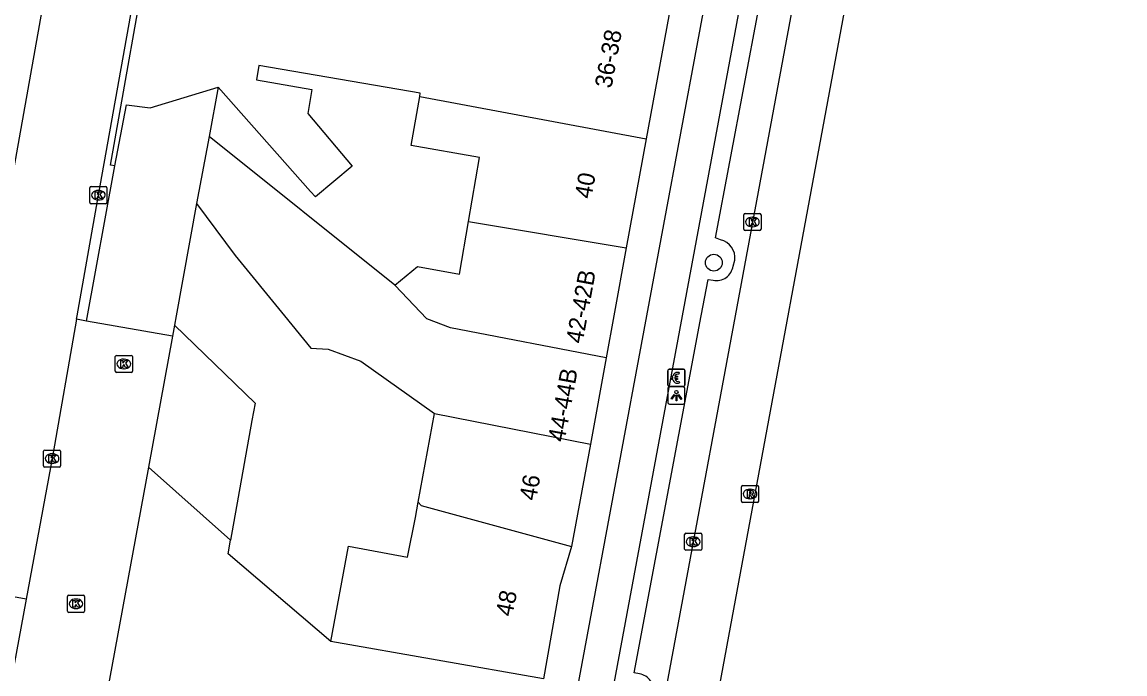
# Model space of a CAD drawing. Extents: x 161402 to 161933, y 381650 to 382313.
# Drawn here: x 161862.2 to 161926.7, y 381979.1 to 382017.2 of the extents above; entities that cross this region are included whole.
import ezdxf

# ---------------------------------------------------------------- set-up
doc = ezdxf.new("R2010")
doc.units = 0
for name, color, linetype in [('IMGEO_Betaalautomaat', 7, 'Continuous'), ('IMGEO_Boom', 7, 'Continuous'), ('IMGEO_Fietspad_gesloten', 7, 'Continuous'), ('IMGEO_Kolk', 7, 'Continuous'), ('IMGEO_Lichtpunt', 7, 'Continuous'), ('IMGEO_Muur', 7, 'Continuous'), ('IMGEO_OVBaan_gesloten', 7, 'Continuous'), ('IMGEO_Pand', 7, 'Continuous'), ('IMGEO_Pand_nummerreeks', 7, 'Continuous'), ('IMGEO_Parkeervlak_open', 7, 'Continuous'), ('IMGEO_Rijbaan_lokaal_gesloten', 7, 'Continuous'), ('IMGEO_Rijbaan_lokaal_open', 7, 'Continuous'), ('IMGEO_Rioolput', 7, 'Continuous')]:
    doc.layers.add(name, color=color, linetype=linetype)

msp = doc.modelspace()

# ---------------------------------------------------------------- linework, layer by layer
at = {"layer": 'IMGEO_Betaalautomaat'}
for p, q in [((161899.985, 381995.955), (161899.985, 381996.796)), ((161899.985, 381996.796), (161899.985, 381995.955)), ((161900.06, 381996.879), (161900.901, 381996.879)), ((161900.901, 381996.879), (161900.06, 381996.879)), ((161900.984, 381996.805), (161900.984, 381995.964)), ((161900.984, 381995.964), (161900.984, 381996.805)), ((161900.268, 381996.343), (161900.268, 381996.411)), ((161900.389, 381996.411), (161900.389, 381996.343)), ((161900.647, 381996.684), (161900.63, 381996.584)), ((161900.634, 381996.178), (161900.656, 381996.091)), ((161900.91, 381995.88), (161900.069, 381995.88)), ((161900.069, 381995.88), (161900.91, 381995.88))]:
    msp.add_line(p, q, dxfattribs=at)
for points in [[(161900.268, 381996.411), (161900.199, 381996.411), (161900.199, 381996.48), (161900.278, 381996.48)], [(161900.273, 381996.274), (161900.199, 381996.274), (161900.199, 381996.343), (161900.268, 381996.343)], [(161900.4, 381996.48), (161900.547, 381996.48), (161900.547, 381996.411), (161900.389, 381996.411)], [(161900.389, 381996.343), (161900.547, 381996.343), (161900.547, 381996.274), (161900.403, 381996.274)]]:
    msp.add_lwpolyline(points, dxfattribs=at)
for centre, radius, start, end in [((161900.063, 381996.802), 0.0779, 92.4484, 184.28452), ((161900.063, 381996.802), 0.0779, 92.4484, 184.28452), ((161900.907, 381996.802), 0.0779, 2.4484, 94.28452), ((161900.907, 381996.802), 0.0779, 2.4484, 94.28452), ((161900.534, 381996.329), 0.267, 191.80956, 297.03891), ((161900.561, 381996.404), 0.293, 73.01398, 165.01395), ((161900.567, 381996.417), 0.179, 69.32359, 159.56827), ((161900.567, 381996.344), 0.179, 202.76249, 291.86925), ((161900.063, 381995.958), 0.0779, 182.4484, 274.28452), ((161900.063, 381995.958), 0.0779, 182.4484, 274.28452), ((161900.907, 381995.958), 0.0779, 272.4484, 4.28452), ((161900.907, 381995.958), 0.0779, 272.4484, 4.28452)]:
    msp.add_arc(centre, radius, start, end, dxfattribs=at)
at = {"layer": 'IMGEO_Boom'}
msp.add_circle((161902.671, 382003.107), 0.489, dxfattribs=at)
at = {"layer": 'IMGEO_Fietspad_gesloten'}
for points in [[(161869.899, 381834.602), (161881.54, 381896.271), (161882.623, 381902.093), (161888.398, 381933.147), (161890.059, 381942.083), (161900.83, 382000), (161908.061, 382038.88), (161912.039, 382060.567)], [(161887.89, 381941.593), (161898.752, 382000), (161905.702, 382037.375), (161910.061, 382061.001)]]:
    msp.add_lwpolyline(points, dxfattribs=at)
at = {"layer": 'IMGEO_Kolk'}
for p, q in [((161866.202, 382006.623), (161866.202, 382007.475)), ((161866.277, 382007.549), (161867.129, 382007.549)), ((161866.69, 382007.329), (161866.715, 382007.329)), ((161867.203, 382007.475), (161867.203, 382006.623)), ((161867.129, 382006.549), (161866.277, 382006.549)), ((161866.713, 382006.769), (161866.688, 382006.769)), ((161904.427, 382005.056), (161904.427, 382005.908)), ((161904.502, 382005.982), (161905.354, 382005.982)), ((161904.915, 382005.762), (161904.94, 382005.762)), ((161905.428, 382005.908), (161905.428, 382005.056)), ((161904.938, 382005.202), (161904.913, 382005.202)), ((161905.354, 382004.982), (161904.502, 382004.982)), ((161867.692, 381996.764), (161867.692, 381997.616)), ((161867.767, 381997.69), (161868.619, 381997.69)), ((161868.18, 381997.47), (161868.205, 381997.47)), ((161868.693, 381997.616), (161868.693, 381996.764)), ((161868.203, 381996.91), (161868.178, 381996.91)), ((161868.619, 381996.69), (161867.767, 381996.69)), ((161863.496, 381991.235), (161863.496, 381992.087)), ((161863.571, 381992.161), (161864.423, 381992.161)), ((161863.984, 381991.941), (161864.009, 381991.941)), ((161864.497, 381992.087), (161864.497, 381991.235)), ((161864.423, 381991.161), (161863.571, 381991.161)), ((161864.007, 381991.381), (161863.982, 381991.381)), ((161900.963, 381986.38), (161900.963, 381987.232)), ((161901.038, 381987.306), (161901.89, 381987.306)), ((161901.451, 381987.086), (161901.476, 381987.086)), ((161901.964, 381987.232), (161901.964, 381986.38)), ((161901.474, 381986.526), (161901.449, 381986.526)), ((161901.89, 381986.306), (161901.038, 381986.306)), ((161864.896, 381982.754), (161864.896, 381983.606)), ((161864.971, 381983.68), (161865.823, 381983.68)), ((161865.384, 381983.46), (161865.409, 381983.46)), ((161865.897, 381983.606), (161865.897, 381982.754)), ((161865.823, 381982.68), (161864.971, 381982.68)), ((161865.407, 381982.9), (161865.382, 381982.9))]:
    msp.add_line(p, q, dxfattribs=at)
for points in [[(161866.202, 382006.623), (161866.202, 382007.475)], [(161866.277, 382007.549), (161867.129, 382007.549)], [(161866.523, 382007.249), (161866.646, 382007.249), (161866.646, 382007.098), (161866.776, 382007.249), (161866.94, 382007.249), (161866.794, 382007.098), (161866.947, 382006.849), (161866.795, 382006.849), (161866.71, 382007.013), (161866.646, 382006.946), (161866.646, 382006.849), (161866.523, 382006.849), (161866.523, 382007.249)], [(161867.203, 382007.475), (161867.203, 382006.623)], [(161867.129, 382006.549), (161866.277, 382006.549)], [(161904.427, 382005.056), (161904.427, 382005.908)], [(161904.502, 382005.982), (161905.354, 382005.982)], [(161905.428, 382005.908), (161905.428, 382005.056)], [(161904.748, 382005.682), (161904.871, 382005.682), (161904.871, 382005.531), (161905.001, 382005.682), (161905.165, 382005.682), (161905.019, 382005.531), (161905.172, 382005.282), (161905.02, 382005.282), (161904.935, 382005.446), (161904.871, 382005.379), (161904.871, 382005.282), (161904.748, 382005.282), (161904.748, 382005.682)], [(161905.354, 382004.982), (161904.502, 382004.982)], [(161867.692, 381996.764), (161867.692, 381997.616)], [(161867.767, 381997.69), (161868.619, 381997.69)], [(161868.013, 381997.39), (161868.136, 381997.39), (161868.136, 381997.239), (161868.266, 381997.39), (161868.43, 381997.39), (161868.284, 381997.239), (161868.437, 381996.99), (161868.285, 381996.99), (161868.2, 381997.154), (161868.136, 381997.087), (161868.136, 381996.99), (161868.013, 381996.99), (161868.013, 381997.39)], [(161868.693, 381997.616), (161868.693, 381996.764)], [(161868.619, 381996.69), (161867.767, 381996.69)], [(161863.496, 381991.235), (161863.496, 381992.087)], [(161863.571, 381992.161), (161864.423, 381992.161)], [(161863.817, 381991.861), (161863.94, 381991.861), (161863.94, 381991.71), (161864.07, 381991.861), (161864.234, 381991.861), (161864.088, 381991.71), (161864.241, 381991.461), (161864.089, 381991.461), (161864.004, 381991.625), (161863.94, 381991.558), (161863.94, 381991.461), (161863.817, 381991.461), (161863.817, 381991.861)], [(161864.497, 381992.087), (161864.497, 381991.235)], [(161864.423, 381991.161), (161863.571, 381991.161)], [(161900.963, 381986.38), (161900.963, 381987.232)], [(161901.038, 381987.306), (161901.89, 381987.306)], [(161901.964, 381987.232), (161901.964, 381986.38)], [(161901.284, 381987.006), (161901.407, 381987.006), (161901.407, 381986.855), (161901.537, 381987.006), (161901.701, 381987.006), (161901.555, 381986.855), (161901.708, 381986.606), (161901.556, 381986.606), (161901.471, 381986.77), (161901.407, 381986.703), (161901.407, 381986.606), (161901.284, 381986.606), (161901.284, 381987.006)], [(161901.89, 381986.306), (161901.038, 381986.306)], [(161864.896, 381982.754), (161864.896, 381983.606)], [(161864.971, 381983.68), (161865.823, 381983.68)], [(161865.217, 381983.38), (161865.34, 381983.38), (161865.34, 381983.229), (161865.47, 381983.38), (161865.634, 381983.38), (161865.488, 381983.229), (161865.641, 381982.98), (161865.489, 381982.98), (161865.404, 381983.144), (161865.34, 381983.077), (161865.34, 381982.98), (161865.217, 381982.98), (161865.217, 381983.38)], [(161865.897, 381983.606), (161865.897, 381982.754)], [(161865.823, 381982.68), (161864.971, 381982.68)]]:
    msp.add_lwpolyline(points, dxfattribs=at)
for centre, start, end in [((161866.279, 382007.473), 91.55205, 178.44795), ((161866.279, 382007.473), 91.55205, 178.44795), ((161867.127, 382007.473), 1.55205, 88.44795), ((161867.127, 382007.473), 1.55205, 88.44795), ((161866.279, 382006.625), 181.55205, 268.44795), ((161866.279, 382006.625), 181.55205, 268.44795), ((161867.127, 382006.625), 271.55205, 358.44795), ((161867.127, 382006.625), 271.55205, 358.44795), ((161904.504, 382005.906), 91.55205, 178.44795), ((161904.504, 382005.906), 91.55205, 178.44795), ((161905.352, 382005.906), 1.55205, 88.44795), ((161905.352, 382005.906), 1.55205, 88.44795), ((161904.504, 382005.058), 181.55205, 268.44795), ((161904.504, 382005.058), 181.55205, 268.44795), ((161905.352, 382005.058), 271.55205, 358.44795), ((161905.352, 382005.058), 271.55205, 358.44795), ((161867.769, 381997.614), 91.55205, 178.44795), ((161867.769, 381997.614), 91.55205, 178.44795), ((161868.617, 381997.614), 1.55205, 88.44795), ((161868.617, 381997.614), 1.55205, 88.44795), ((161867.769, 381996.766), 181.55205, 268.44795), ((161867.769, 381996.766), 181.55205, 268.44795), ((161868.617, 381996.766), 271.55205, 358.44795), ((161868.617, 381996.766), 271.55205, 358.44795), ((161863.573, 381992.085), 91.55205, 178.44795), ((161863.573, 381992.085), 91.55205, 178.44795), ((161864.421, 381992.085), 1.55205, 88.44795), ((161864.421, 381992.085), 1.55205, 88.44795), ((161863.573, 381991.237), 181.55205, 268.44795), ((161863.573, 381991.237), 181.55205, 268.44795), ((161864.421, 381991.237), 271.55205, 358.44795), ((161864.421, 381991.237), 271.55205, 358.44795), ((161901.04, 381987.23), 91.55205, 178.44795), ((161901.04, 381987.23), 91.55205, 178.44795), ((161901.888, 381987.23), 1.55205, 88.44795), ((161901.888, 381987.23), 1.55205, 88.44795), ((161901.04, 381986.382), 181.55205, 268.44795), ((161901.04, 381986.382), 181.55205, 268.44795), ((161901.888, 381986.382), 271.55205, 358.44795), ((161901.888, 381986.382), 271.55205, 358.44795), ((161864.973, 381983.604), 91.55205, 178.44795), ((161864.973, 381983.604), 91.55205, 178.44795), ((161865.821, 381983.604), 1.55205, 88.44795), ((161865.821, 381983.604), 1.55205, 88.44795), ((161864.973, 381982.756), 181.55205, 268.44795), ((161864.973, 381982.756), 181.55205, 268.44795), ((161865.821, 381982.756), 271.55205, 358.44795), ((161865.821, 381982.756), 271.55205, 358.44795)]:
    msp.add_arc(centre, 0.0765, start, end, dxfattribs=at)
for centre, major_axis, ratio, start_param, end_param in [((161866.689, 382007.049), (-0.387, 0.002), 0.722429, 4.712389, 7.853982), ((161866.714, 382007.049), (-0.39, 0.002), 0.717154, 1.570796, 4.712389), ((161904.914, 382005.482), (-0.387, 0.002), 0.722429, 4.712389, 7.853982), ((161904.939, 382005.482), (-0.39, 0.002), 0.717154, 1.570796, 4.712389), ((161868.179, 381997.19), (-0.387, 0.002), 0.722429, 4.712389, 7.853982), ((161868.204, 381997.19), (-0.39, 0.002), 0.717154, 1.570796, 4.712389), ((161863.983, 381991.661), (-0.387, 0.002), 0.722429, 4.712389, 7.853982), ((161864.008, 381991.661), (-0.39, 0.002), 0.717154, 1.570796, 4.712389), ((161901.45, 381986.806), (-0.387, 0.002), 0.722429, 4.712389, 7.853982), ((161901.475, 381986.806), (-0.39, 0.002), 0.717154, 1.570796, 4.712389), ((161865.383, 381983.18), (-0.387, 0.002), 0.722429, 4.712389, 7.853982), ((161865.408, 381983.18), (-0.39, 0.002), 0.717154, 1.570796, 4.712389)]:
    msp.add_ellipse(centre, major_axis=major_axis, ratio=ratio, start_param=start_param, end_param=end_param, dxfattribs=at)
at = {"layer": 'IMGEO_Lichtpunt'}
for p, q in [((161899.984, 381995.75), (161899.984, 381994.943)), ((161899.984, 381995.75), (161899.984, 381994.943)), ((161900.886, 381995.845), (161900.078, 381995.845)), ((161900.886, 381995.845), (161900.078, 381995.845)), ((161900.98, 381994.943), (161900.98, 381995.75)), ((161900.98, 381994.943), (161900.98, 381995.75)), ((161900.078, 381994.849), (161900.886, 381994.849)), ((161900.078, 381994.849), (161900.886, 381994.849))]:
    msp.add_line(p, q, dxfattribs=at)
for points in [[(161900.358, 381995.414), (161900.397, 381995.386), (161900.209, 381995.124), (161900.171, 381995.151), (161900.358, 381995.414)], [(161900.57, 381995.386), (161900.608, 381995.413), (161900.795, 381995.151), (161900.756, 381995.123), (161900.57, 381995.386)], [(161900.46, 381995.366), (161900.507, 381995.366), (161900.507, 381995.044), (161900.46, 381995.044), (161900.46, 381995.366)]]:
    msp.add_lwpolyline(points, dxfattribs=at)
msp.add_circle((161900.483, 381995.548), 0.0994, dxfattribs=at)
for centre, start, end in [((161900.078, 381995.75), 90, 180), ((161900.078, 381995.75), 90, 180), ((161900.886, 381995.75), 0, 90), ((161900.886, 381995.75), 0, 90), ((161900.078, 381994.943), 180, 270), ((161900.078, 381994.943), 180, 270), ((161900.886, 381994.943), 270, 0), ((161900.886, 381994.943), 270, 360)]:
    msp.add_arc(centre, 0.0946, start, end, dxfattribs=at)
at = {"layer": 'IMGEO_Muur'}
for points in [[(161865.428, 381999.797), (161865.464, 382000), (161866.704, 382007.049), (161869.364, 382021.87), (161869.415, 382022.052), (161864.341, 382023.003)], [(161866.018, 381999.693), (161867.662, 382008.757)], [(161866.018, 381999.693), (161865.428, 381999.797)]]:
    msp.add_lwpolyline(points, dxfattribs=at)
at = {"layer": 'IMGEO_OVBaan_gesloten'}
msp.add_lwpolyline([(161894.174, 381930.698), (161920.066, 382070.485), (161920.568, 382072.989), (161920.797, 382074.121), (161926.695, 382099.95)], dxfattribs=at)
at = {"layer": 'IMGEO_Pand'}
for points in [[(161867.662, 382008.757), (161867.411, 382008.805), (161869.815, 382022.328), (161863.131, 382023.567)], [(161900.585, 382020.509), (161898.721, 382010.338)], [(161885.484, 382012.805), (161885.518, 382013.001), (161876.089, 382014.631), (161875.942, 382013.78), (161879.179, 382013.22), (161878.935, 382011.811), (161881.528, 382008.741), (161879.399, 382006.944), (161879.107, 382007.258), (161873.713, 382013.349)], [(161867.662, 382008.757), (161868.345, 382012.335), (161869.732, 382012.161), (161873.713, 382013.349)], [(161888.339, 382005.521), (161888.984, 382009.253), (161884.99, 382009.944), (161885.484, 382012.805)], [(161885.484, 382012.805), (161898.721, 382010.338)], [(161873.17, 382010.475), (161872.441, 382006.571)], [(161884.026, 382001.783), (161873.17, 382010.475)], [(161898.721, 382010.338), (161897.556, 382003.977)], [(161872.441, 382006.571), (161874.692, 382003.53), (161877.576, 382000), (161879.115, 381998.117), (161880.142, 381998.056), (161882.034, 381997.356), (161886.356, 381994.299)], [(161884.026, 382001.783), (161885.351, 382002.88), (161887.804, 382002.429), (161888.339, 382005.521)], [(161888.339, 382005.521), (161897.556, 382003.977)], [(161897.556, 382003.977), (161896.827, 382000), (161896.379, 381997.555)], [(161896.379, 381997.555), (161887.286, 381999.308), (161885.901, 381999.826), (161884.026, 382001.783)], [(161871.144, 381999.457), (161871.026, 381998.811)], [(161871.144, 381999.457), (161875.859, 381994.892), (161875.679, 381993.882), (161874.432, 381986.902)], [(161871.026, 381998.811), (161869.626, 381991.167)], [(161896.379, 381997.555), (161895.455, 381992.511)], [(161885.393, 381989.112), (161886.356, 381994.299)], [(161886.356, 381994.299), (161895.455, 381992.511)], [(161895.455, 381992.511), (161894.351, 381986.526)], [(161869.626, 381991.167), (161866.912, 381976.352)], [(161874.432, 381986.902), (161869.626, 381991.167)], [(161880.283, 381980.984), (161881.327, 381986.546), (161884.769, 381985.9), (161885.227, 381988.221), (161885.393, 381989.112)], [(161885.393, 381989.112), (161885.565, 381988.922), (161894.351, 381986.526)], [(161880.283, 381980.984), (161874.288, 381986.095), (161874.432, 381986.902)], [(161894.351, 381986.526), (161893.665, 381984.233), (161892.707, 381978.796)], [(161892.707, 381978.796), (161880.283, 381980.984)]]:
    msp.add_lwpolyline(points, dxfattribs=at)
at = {"layer": 'IMGEO_Parkeervlak_open'}
for points in [[(161903.065, 382004.44), (161902.77, 382004.559), (161905.275, 382017.882), (161905.552, 382017.835)], [(161903.796, 382002.91), (161903.898, 382003.256)], [(161898.32, 381979.083), (161898.016, 381979.138), (161901.937, 382000), (161902.336, 382002.121), (161902.629, 382002.08)]]:
    msp.add_lwpolyline(points, dxfattribs=at)
for centre, radius, start, end in [((161902.829, 382003.389), 1.077, 352.89806, 77.35834), ((161902.817, 382003.051), 0.989, 259.06008, 351.78273), ((161898.185, 381978.134), 0.958, 346.34412, 81.88699)]:
    msp.add_arc(centre, radius, start, end, dxfattribs=at)
at = {"layer": 'IMGEO_Rijbaan_lokaal_gesloten'}
for points in [[(161917.217, 382071.563), (161910.924, 382037.806), (161903.912, 382000), (161894.985, 381951.871)], [(161862.491, 381983.458), (161857.448, 381984.357), (161864.341, 382023.003)], [(161862.491, 381983.458), (161861.636, 381978.805), (161861.321, 381976.94)]]:
    msp.add_lwpolyline(points, dxfattribs=at)
at = {"layer": 'IMGEO_Rijbaan_lokaal_open'}
for points in [[(161873.713, 382013.349), (161873.17, 382010.475)], [(161872.441, 382006.571), (161871.243, 382000), (161871.144, 381999.457)], [(161865.428, 381999.797), (161863.999, 381991.661), (161862.491, 381983.458)], [(161871.026, 381998.811), (161866.018, 381999.693)]]:
    msp.add_lwpolyline(points, dxfattribs=at)
at = {"layer": 'IMGEO_Rioolput'}
for p, q in [((161904.289, 381989.168), (161904.289, 381990.02)), ((161904.364, 381990.094), (161905.216, 381990.094)), ((161904.777, 381989.874), (161904.802, 381989.874)), ((161905.29, 381990.02), (161905.29, 381989.168)), ((161905.216, 381989.094), (161904.364, 381989.094)), ((161904.8, 381989.314), (161904.775, 381989.314))]:
    msp.add_line(p, q, dxfattribs=at)
for points in [[(161904.289, 381989.168), (161904.289, 381990.02)], [(161904.364, 381990.094), (161905.216, 381990.094)], [(161904.878, 381989.792), (161904.626, 381989.794), (161904.626, 381989.394)], [(161904.804, 381989.713), (161904.75, 381989.713), (161904.75, 381989.632)], [(161904.75, 381989.632), (161904.802, 381989.632)], [(161905.29, 381990.02), (161905.29, 381989.168)], [(161905.216, 381989.094), (161904.364, 381989.094)], [(161904.626, 381989.394), (161904.75, 381989.394), (161904.75, 381989.556), (161904.761, 381989.556)], [(161904.808, 381989.527), (161904.879, 381989.394), (161905.019, 381989.394), (161904.954, 381989.52)]]:
    msp.add_lwpolyline(points, dxfattribs=at)
for centre, radius, start, end in [((161904.366, 381990.018), 0.0765, 91.55205, 178.44795), ((161904.366, 381990.018), 0.0765, 91.55205, 178.44795), ((161904.786, 381989.821), 0.19, 274.7715, 282.96867), ((161904.81, 381989.617), 0.0964, 77.00612, 93.18647), ((161904.824, 381989.674), 0.0378, 276.66336, 79.67722), ((161904.877, 381989.682), 0.109, 350.36119, 89.41601), ((161904.875, 381989.682), 0.112, 277.58423, 350.98172), ((161905.214, 381990.018), 0.0765, 1.55205, 88.44795), ((161905.214, 381990.018), 0.0765, 1.55205, 88.44795), ((161904.366, 381989.17), 0.0765, 181.55205, 268.44795), ((161904.366, 381989.17), 0.0765, 181.55205, 268.44795), ((161904.76, 381989.503), 0.0533, 26.02933, 88.69889), ((161904.859, 381989.467), 0.108, 29.51342, 73.79051), ((161905.214, 381989.17), 0.0765, 271.55205, 358.44795), ((161905.214, 381989.17), 0.0765, 271.55205, 358.44795)]:
    msp.add_arc(centre, radius, start, end, dxfattribs=at)
for centre, major_axis, ratio, start_param, end_param in [((161904.776, 381989.594), (-0.387, 0.002), 0.722429, 4.712389, 7.853982), ((161904.801, 381989.594), (-0.39, 0.002), 0.717154, 1.570796, 4.712389)]:
    msp.add_ellipse(centre, major_axis=major_axis, ratio=ratio, start_param=start_param, end_param=end_param, dxfattribs=at)

# ---------------------------------------------------------------- texts
at = {"layer": 'IMGEO_Pand_nummerreeks'}
for s, rotation, p in [('36-38', 79.54481, (161896.684, 382013.253)), ('40', 79.73281, (161895.506, 382006.798)), ('42-42B', 79.61249, (161894.998, 381998.34)), ('44-44B', 79.61822, (161893.945, 381992.593)), ('46', 79.54864, (161892.274, 381989.163)), ('48', 78.35544, (161890.882, 381982.391))]:
    msp.add_text(s, height=1, rotation=rotation, dxfattribs=at).set_placement(p)

doc.saveas('drawing.dxf')
